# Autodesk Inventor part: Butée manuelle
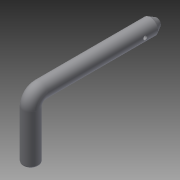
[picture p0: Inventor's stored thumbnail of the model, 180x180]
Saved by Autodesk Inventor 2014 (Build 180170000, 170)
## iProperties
Created: 2015-09
Part Number: Butée manuelle
Material: Générique
Document SubType Name: Modeling
Designer: OL
Density: 1 g/cm^3
Appearance: Par défaut
Author: OL
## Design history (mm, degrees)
sketch "Esquisse1"
  geometry: L1 (0, 0)-(-120, 0); L2 (-130, -10)-(-130, -60); A1 r 10 centre (-120, -10) between (-120, 0) and (-130, -10); 1 further point
  constraints: 4 end point, 2 point on circle, 2 point on line, 2 tangent, 1 centre point, 1 horizontal, 1 perpendicular
  dimensions: "d0" = 130 distance of L1.start point (-130, 0); "d1" = 60 distance of point (-130, 0) L2.end; "d2" = 10 radius of A1
sketch "Esquisse2"
  geometry: C1 r 8 at (0, 0); 1 further point
  constraints: 1 centre point, 1 coincident
  dimensions: "d3" = 16 diameter of C1
feature "Balayage1" sketch "Esquisse1", "Esquisse2" dims "d5" = 0
chamfer "Chanfrein1" distance "d6" = 7; stored, may be unused: second distance "d7" = 4, angle "d8" = 45 deg
fillet "Congé1" dims "d9" = 2
sketch "Esquisse3"
  geometry: L1 (0, 4)-(0, -4) reference; C1 r 2 at (-20, 0); 1 further point
  constraints: 1 centre point
  dimensions: "d10" = 4 diameter of C1; "d12" = 20 distance from line of L1 C1.centre
extrude "Extrusion1" cut sketch "Esquisse3" stored distance "d13" = 20; taper "d14" = 0 deg
node "Solide1"
